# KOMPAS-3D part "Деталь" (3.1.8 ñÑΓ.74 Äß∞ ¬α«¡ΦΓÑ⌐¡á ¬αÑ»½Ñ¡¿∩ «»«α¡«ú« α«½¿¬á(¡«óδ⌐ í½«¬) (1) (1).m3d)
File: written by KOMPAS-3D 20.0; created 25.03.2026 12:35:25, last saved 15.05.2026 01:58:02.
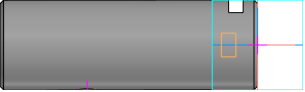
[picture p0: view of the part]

Document properties: Автор: TMK; Полное имя файла: E:\test_kompas\all_v18\3.1.8 дет.74 Ось кронштейна крепления опорного ролика(новый блок) (1) (1).m3d; Организация: TMK

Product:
- Part/product: Деталь
    Масса: 2.04624
  - Body: Тело 1

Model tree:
1. Эскиз:1
2. Элемент выдавливания:1
     Расстояние 2 = 142
3. Фаска:1
     Угол = 45; Длина 1 = 2; Длина 2 = 2
4. Эскиз:2
5. Отверстие:2  (with: Элемент выдавливания:1)
     Глубина выреза = 99.5; Диаметр отверстия = 11.4448; Угол конуса дна = 118; Диаметр цековки = 23; Глубина цековки = 12
6. G 1/4  (with: Отверстие:2)
     Длина резьбы = 20; Шаг резьбы = 1.337; Номинальный диаметр резьбы = 13.157
7. Фаска:2
     Угол = 45; Длина 1 = 1.6; Длина 2 = 1.6
8. Смещенная плоскость:2
     Расстояние = 25
9. Эскиз:4
10. Отверстие:3
     Глубина выреза = 30.5; Диаметр отверстия = 11.5; Угол конуса дна = 118; Расстояние 2 = -94
11. Смещенная плоскость:3
     Расстояние = 25
12. Эскиз:5
13. Элемент выдавливания:3
     Расстояние 2 = 50

Expressions: cil2_6357-81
